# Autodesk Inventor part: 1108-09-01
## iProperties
Created: 2007-03
Part Number: 1108-09-01
Document SubType Name: Modeling
Designer: Andy Moles
Material: Steel
Mass: 17.8465 g
Surface Area: 26.822 cm^2
Volume: 2.27344 cm^3
Density: 7.85 g/cm^3
Author: Andy Moles
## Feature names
1. Base1
